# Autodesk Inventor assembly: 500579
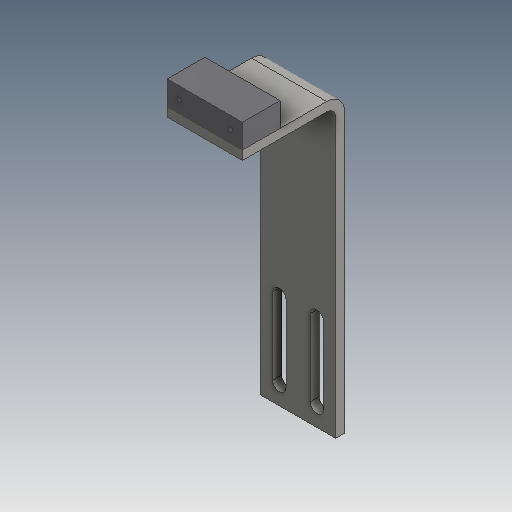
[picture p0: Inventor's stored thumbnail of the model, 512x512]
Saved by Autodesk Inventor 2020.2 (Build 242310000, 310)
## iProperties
Created: 2000-02
Part Number: 500579
Description: WMT-CP,FH,XX,MNT,PLOW
Document SubType Name: Assembly
Designer: sspink
Mass: 225.918 g
Surface Area: 337.937 cm^2
Volume: 90.0912 cm^3
Density: 2.50766 g/cm^3
Control State: 0
Checked Out: False
Master: False
Shininess: 0.0
Length Units: 11269
Angle Units: 11279
Time Units: 11290
Mass Units: 11283
Length Display Precision: 3
Angle Display Precision: 2
Compacted: True
Dimensions: 213x68x50 mm
Mass: 0,226 kg
Density: 0.0
Volumn: 0.0
Area: 0.0
PropertySet Name: Model Information
Author: sspink
Revision Number: -
Title: WMT-CP,FH,XX,MNT,PLOW
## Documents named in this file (3)
- D:\07 - DEMODATEN\OTX 2019 - Dataset - UPDATE - Dez2019\Designs\07-Packing machine\500579.iam
- D:\07 - DEMODATEN\OTX 2019 - Dataset - UPDATE - Dez2019\Designs\07-Packing machine\Parts\ADSK-011513.ipt
- D:\07 - DEMODATEN\OTX 2019 - Dataset - UPDATE - Dez2019\Designs\07-Packing machine\Parts\ADSK-011514.ipt
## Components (2 placed, 2 different names)
1. ADSK-011513:1 — Passend:1, Passend:2, Fluchtend:1
2. ADSK-011514:1 — Passend:1, Passend:2, Fluchtend:1
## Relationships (3: Mate 2, Flush 1)
- Passend:1 [Mate]: ADSK-011513:1 ↔ ADSK-011514:1
- Passend:2 [Mate]: ADSK-011513:1 ↔ ADSK-011514:1
- Fluchtend:1 [Flush]: ADSK-011513:1 ↔ ADSK-011514:1
